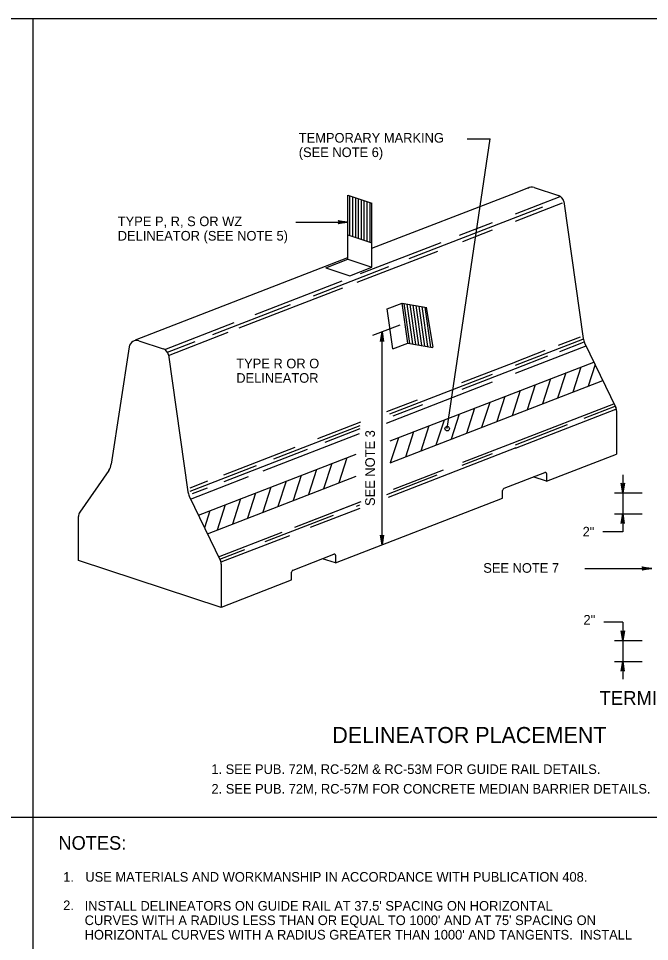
# Model space of a CAD drawing. Extents: x 640253 to 641999, y 298458 to 299646.
# Drawn here: x 640796.8 to 640993.6, y 298748.9 to 299036.6 of the extents above; entities that cross this region are included whole.
import ezdxf

# ---------------------------------------------------------------- set-up
doc = ezdxf.new("R2010")
doc.units = 0
doc.layers.add('1', color=7, linetype='Continuous')
doc.layers.add('2', color=7, linetype='Continuous')

msp = doc.modelspace()

# ---------------------------------------------------------------- linework, layer by layer
at = {"layer": '1'}
for p, q in [((640293.31, 299036.63), (641079.31, 299036.63)), ((640801.38, 298472.63), (640801.38, 299036.63)), ((640293.31, 298787.67), (641079.31, 298787.67))]:
    msp.add_line(p, q, dxfattribs=at)
at = {"layer": '2'}
for p, q in [((640930.48, 298908.79), (640943.83, 298999.15)), ((640936.73, 298999.15), (640943.83, 298999.15)), ((640907.03, 298965), (640951.73, 298982.3)), ((640951.73, 298982.3), (640956.11, 298984)), ((640957.62, 298983.95), (640965.2, 298981.46)), ((640899.54, 298961.59), (640899.54, 298981.54)), ((640899.54, 298981.54), (640907.03, 298979.08)), ((640900.15, 298968.95), (640900.15, 298981.34)), ((640901.05, 298968.66), (640901.05, 298981.04)), ((640901.95, 298968.36), (640901.95, 298980.75)), ((640902.85, 298968.07), (640902.85, 298980.45)), ((640903.75, 298967.77), (640903.75, 298980.16)), ((640904.65, 298967.47), (640904.65, 298979.86)), ((640905.55, 298967.18), (640905.55, 298979.57)), ((640906.45, 298966.89), (640906.45, 298979.27)), ((640951.73, 298975.77), (640965.71, 298981.18)), ((640966.81, 298979.57), (640972.89, 298936.9)), ((640907.03, 298959.13), (640907.03, 298979.08)), ((640918.67, 298961.77), (640960.33, 298977.89)), ((640951.73, 298973.49), (640966.43, 298979.19)), ((640883.31, 298973.12), (640899.54, 298973.12)), ((640934.34, 298969.05), (640944.63, 298973.03)), ((640935.32, 298967.14), (640944.63, 298970.75)), ((640899.54, 298969.15), (640907.03, 298966.7)), ((640903.5, 298957.11), (640928.55, 298966.8)), ((640833.28, 298936.45), (640899.54, 298962.1)), ((640902.44, 298954.42), (640927.55, 298964.14)), ((640888.78, 298950.2), (640912.25, 298959.29)), ((640892.6, 298958.9), (640899.54, 298961.59)), ((640899.54, 298961.59), (640907.03, 298959.13)), ((640900.09, 298956.45), (640907.03, 298959.13)), ((640892.6, 298958.9), (640900.09, 298956.45)), ((640870.62, 298944.4), (640897.74, 298954.86)), ((640865.65, 298940.18), (640897.97, 298952.69)), ((640911.77, 298946.1), (640916.42, 298947.9)), ((640918.23, 298935.45), (640916.42, 298947.9)), ((640916.42, 298947.9), (640924.18, 298946.55)), ((640918.86, 298935.34), (640917.05, 298947.8)), ((640919.79, 298935.18), (640917.98, 298947.63)), ((640857.44, 298938.14), (640881.63, 298947.51)), ((640913.58, 298933.64), (640911.77, 298946.1)), ((640920.73, 298935.01), (640918.92, 298947.47)), ((640921.66, 298934.85), (640919.85, 298947.31)), ((640922.59, 298934.69), (640920.78, 298947.14)), ((640923.53, 298934.53), (640921.72, 298946.98)), ((640924.46, 298934.36), (640922.65, 298946.82)), ((640925.39, 298934.2), (640923.58, 298946.65)), ((640926.07, 298934.14), (640924, 298946.55)), ((640842.48, 298933.48), (640864.06, 298941.84)), ((640907.33, 298937.88), (640915.87, 298941.19)), ((640910.16, 298872.55), (640910.16, 298938.98)), ((640834.4, 298936.2), (640841.97, 298933.71)), ((640843.59, 298931.63), (640862.22, 298938.84)), ((640951.73, 298928.54), (640972.74, 298936.66)), ((640965.17, 298934.8), (640972.01, 298937.43)), ((640831.35, 298934.32), (640825.77, 298897.72)), ((640843.3, 298932.64), (640851.92, 298935.99)), ((640913.58, 298933.64), (640918.23, 298935.45)), ((640918.23, 298935.45), (640926, 298934.1)), ((640951.73, 298926.06), (640973.75, 298934.58)), ((640951.73, 298929.6), (640961.03, 298933.2)), ((640965.56, 298932.85), (640972.98, 298935.73)), ((640973.31, 298935.51), (640983.05, 298915.35)), ((640843.56, 298931.81), (640849.66, 298889.14)), ((640951.73, 298927.5), (640961.88, 298931.43)), ((640912.75, 298904.98), (640976.19, 298929.55)), ((640935.08, 298923.15), (640951.84, 298929.63)), ((640935.13, 298921.08), (640951.73, 298927.51)), ((640972.18, 298928), (640969.66, 298920.15)), ((640976.57, 298928.75), (640974.4, 298921.99)), ((640912.6, 298913.39), (640944.63, 298925.78)), ((640967.44, 298926.16), (640964.91, 298918.31)), ((640911.52, 298910.51), (640944.63, 298923.33)), ((640912.75, 298898.11), (640978.99, 298923.76)), ((640957.95, 298922.49), (640955.43, 298914.64)), ((640962.69, 298924.32), (640960.17, 298916.48)), ((640948.47, 298918.81), (640945.95, 298910.97)), ((640953.21, 298920.65), (640950.69, 298912.8)), ((640911.68, 298914.09), (640921.19, 298917.78)), ((640913.67, 298912.78), (640922.86, 298916.32)), ((640943.73, 298916.98), (640941.2, 298909.13)), ((640951.73, 298904.7), (640982.45, 298916.56)), ((640934.24, 298913.3), (640931.72, 298905.46)), ((640938.98, 298915.14), (640936.46, 298907.29)), ((640951.73, 298902.74), (640983.05, 298914.87)), ((640973.21, 298912.07), (640982.82, 298915.81)), ((640983.29, 298914.32), (640983.29, 298900.86)), ((640890.15, 298905.75), (640903.6, 298910.96)), ((640929.5, 298911.47), (640926.98, 298903.62)), ((640876.42, 298899.37), (640903.32, 298909.79)), ((640892.41, 298904.56), (640903.4, 298908.81)), ((640920.01, 298907.79), (640917.49, 298899.95)), ((640924.76, 298909.63), (640922.23, 298901.78)), ((640951.73, 298903.77), (640967.93, 298910.04)), ((640873.14, 298895.63), (640903.14, 298907.25)), ((640915.27, 298905.96), (640912.75, 298898.11)), ((640935.37, 298898.34), (640952.1, 298904.81)), ((640860.9, 298894.44), (640883.13, 298903.03)), ((640860.95, 298892.35), (640886.96, 298902.42)), ((640912.16, 298887.44), (640951.99, 298902.87)), ((640852.95, 298881.82), (640902.12, 298900.87)), ((640899.22, 298899.74), (640896.7, 298891.89)), ((640935.16, 298897.37), (640944.63, 298901.03)), ((640961.42, 298892.38), (640983.29, 298900.86)), ((640850.38, 298889.29), (640871.03, 298897.3)), ((640889.74, 298896.07), (640887.22, 298888.22)), ((640894.48, 298897.9), (640891.96, 298890.06)), ((640913.72, 298889.96), (640929.3, 298895.99)), ((640825.01, 298895.75), (640815.96, 298882.72)), ((640850.45, 298886.85), (640868.5, 298893.85)), ((640855.75, 298876.03), (640902.12, 298893.99)), ((640885, 298894.23), (640882.47, 298886.38)), ((640911.7, 298888.29), (640927.37, 298894.35)), ((640961.42, 298892.38), (640957.3, 298893.74)), ((640985.22, 298894.44), (640985.22, 298876.68)), ((640850.34, 298890.33), (640855.91, 298892.49)), ((640851.13, 298888.56), (640855.81, 298890.38)), ((640875.51, 298890.56), (640872.99, 298882.71)), ((640880.25, 298892.39), (640877.73, 298884.55)), ((640961.42, 298892.39), (640961.42, 298892.39)), ((640850.08, 298887.75), (640859.83, 298867.6)), ((640870.77, 298888.72), (640868.25, 298880.87)), ((640982.63, 298888.75), (640991.3, 298888.75)), ((640861.29, 298885.05), (640858.76, 298877.2)), ((640866.03, 298886.88), (640863.51, 298879.04)), ((640882.95, 298878.05), (640903.7, 298886.08)), ((640882.95, 298878.05), (640903.35, 298885.95)), ((640895.65, 298866.93), (640947.76, 298887.1)), ((640902.25, 298884.65), (640903.23, 298885.02)), ((640856.54, 298883.21), (640854.84, 298877.91)), ((640873.7, 298873.59), (640894.99, 298881.83)), ((640887.9, 298878.04), (640903.35, 298884.03)), ((640982.63, 298882.25), (640991.3, 298882.25)), ((640815.54, 298867.73), (640815.54, 298881.38)), ((640859.22, 298868.86), (640879.09, 298876.55)), ((640985.22, 298876.68), (640979.03, 298876.68)), ((640860, 298867.24), (640881.4, 298875.52)), ((640859.58, 298868.1), (640867.42, 298871.15)), ((640860.06, 298853.07), (640815.54, 298867.73)), ((640895.65, 298866.93), (640891.57, 298868.26)), ((640860.06, 298866.57), (640860.06, 298853.07)), ((640973.4, 298865.2), (640994.25, 298865.2)), ((640860.12, 298853.17), (640881.99, 298861.64)), ((640881.99, 298861.64), (640881.99, 298861.64)), ((640985.22, 298848.44), (640979.3, 298848.44)), ((640985.22, 298848.44), (640985.22, 298830.68)), ((640982.63, 298842.75), (640991.3, 298842.75)), ((640982.63, 298836.25), (640991.3, 298836.25))]:
    msp.add_line(p, q, dxfattribs=at)
for points in [[(640896.69, 298973.48), (640896.79, 298973.28), (640899.54, 298973.12), (640896.69, 298973.48), (640896.54, 298973.61), (640899.54, 298973.12), (640896.8, 298972.99), (640896.7, 298972.79), (640899.54, 298973.12), (640896.54, 298972.65), (640896.7, 298972.79)], [(640909.8, 298936.12), (640910.01, 298936.23), (640910.16, 298938.98), (640909.8, 298936.12), (640909.68, 298935.98), (640910.16, 298938.98), (640910.3, 298936.23), (640910.5, 298936.13), (640910.16, 298938.98), (640910.64, 298935.98), (640910.5, 298936.13)], [(640948.23, 298890.19), (640960.93, 298895.13)], [(640961.42, 298894.78), (640961.42, 298892.38)], [(640985.58, 298891.6), (640985.37, 298891.49), (640985.22, 298888.75), (640985.58, 298891.6), (640985.7, 298891.75), (640985.22, 298888.75), (640985.08, 298891.49), (640984.88, 298891.59), (640985.22, 298888.75), (640984.74, 298891.75), (640984.88, 298891.59)], [(640947.76, 298887.11), (640947.76, 298889.51)], [(640984.86, 298879.39), (640985.06, 298879.5), (640985.22, 298882.25), (640984.86, 298879.39), (640984.73, 298879.25), (640985.22, 298882.25), (640985.35, 298879.5), (640985.56, 298879.4), (640985.22, 298882.25), (640985.69, 298879.25), (640985.56, 298879.4)], [(640910.52, 298875.4), (640910.31, 298875.3), (640910.16, 298872.55), (640910.52, 298875.4), (640910.64, 298875.55), (640910.16, 298872.55), (640910.03, 298875.29), (640909.82, 298875.39), (640910.16, 298872.55), (640909.68, 298875.55), (640909.82, 298875.39)], [(640882.46, 298864.73), (640895.16, 298869.66)], [(640895.65, 298869.32), (640895.65, 298866.93)], [(640991.4, 298865.56), (640991.5, 298865.35), (640994.25, 298865.2), (640991.4, 298865.56), (640991.25, 298865.69), (640994.25, 298865.2), (640991.51, 298865.07), (640991.41, 298864.86), (640994.25, 298865.2), (640991.25, 298864.73), (640991.41, 298864.86)], [(640881.99, 298861.64), (640881.99, 298864.04)], [(640985.58, 298845.6), (640985.37, 298845.49), (640985.22, 298842.75), (640985.58, 298845.6), (640985.7, 298845.75), (640985.22, 298842.75), (640985.08, 298845.49), (640984.88, 298845.59), (640985.22, 298842.75), (640984.74, 298845.75), (640984.88, 298845.59)], [(640984.86, 298833.39), (640985.06, 298833.5), (640985.22, 298836.25), (640984.86, 298833.39), (640984.73, 298833.25), (640985.22, 298836.25), (640985.35, 298833.5), (640985.56, 298833.4), (640985.22, 298836.25), (640985.69, 298833.25), (640985.56, 298833.4)]]:
    msp.add_lwpolyline(points, dxfattribs=at)
msp.add_circle((640930.48, 298908.79), 0.691, dxfattribs=at)
for centre, radius, start, end in [((640956.9, 298981.73), 2.34, 71.7735, 124.6618), ((640964.47, 298979.23), 2.34, 8.1301, 71.7736), ((640833.67, 298933.97), 2.34, 71.7735, 171.3546), ((640977.53, 298937.56), 4.69, 188.13, 205.8211), ((640841.24, 298931.48), 2.34, 8.1301, 71.7736), ((640980.95, 298914.34), 2.34, 0, 25.821), ((640821.15, 298898.43), 4.69, 325.2567, 351.3547), ((640961.06, 298894.79), 0.366, 0, 111.2452), ((640948.49, 298889.51), 0.732, 111.1757, 180), ((640854.3, 298889.81), 4.69, 188.13, 205.8211), ((640817.89, 298881.39), 2.34, 145.2568, 180), ((640857.72, 298866.59), 2.34, 0, 25.821), ((640895.29, 298869.32), 0.366, 0, 111.2554), ((640882.72, 298864.06), 0.732, 111.1757, 180)]:
    msp.add_arc(centre, radius, start, end, dxfattribs=at)

# ---------------------------------------------------------------- texts
for s, height, p in [('TEMPORARY MARKING', 3, (640884.21, 298997.93)), ('(SEE NOTE 6)', 3, (640884.21, 298993.43)), ('TYPE P, R, S OR WZ ', 3, (640827.79, 298971.9)), ('DELINEATOR (SEE NOTE 5)', 3, (640827.79, 298967.4)), ('TYPE R OR O', 3, (640864.73, 298927.59)), ('DELINEATOR', 3, (640864.73, 298923.09)), ('2"', 3, (640972.69, 298875.18)), ('SEE NOTE 7', 3, (640941.72, 298863.87)), ('2"', 3, (640972.96, 298847.72)), ('TERMINAL SECTION DETAIL', 4.3, (640977.99, 298822.71)), ('DELINEATOR PLACEMENT', 5, (640894.66, 298810.81)), ('1. SEE PUB. 72M, RC-52M & RC-53M FOR GUIDE RAIL DETAILS.', 3, (640856.96, 298801.16)), ('2. SEE PUB. 72M, RC-57M FOR CONCRETE MEDIAN BARRIER DETAILS.', 3, (640857, 298795.04)), ('NOTES:', 4.25, (640809.29, 298777.55)), ('1.', 3, (640810.79, 298767.58)), ('USE MATERIALS AND WORKMANSHIP IN ACCORDANCE WITH PUBLICATION 408.', 3, (640817.69, 298767.59)), ('2.', 3, (640810.78, 298758.73)), ("INSTALL DELINEATORS ON GUIDE RAIL AT 37.5' SPACING ON HORIZONTAL ", 3, (640817.48, 298758.57)), ("CURVES WITH A RADIUS LESS THAN OR EQUAL TO 1000' AND AT 75' SPACING ON", 3, (640817.48, 298754.07)), ("HORIZONTAL CURVES WITH A RADIUS GREATER THAN 1000' AND TANGENTS.  INSTALL", 3, (640817.48, 298749.57))]:
    msp.add_text(s, height=height, dxfattribs=at).set_placement(p)
msp.add_text('SEE NOTE 3', height=3, rotation=90, dxfattribs=at).set_placement((640907.94, 298884.68))

doc.saveas('drawing.dxf')
